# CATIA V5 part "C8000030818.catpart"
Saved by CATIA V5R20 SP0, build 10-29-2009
Part number: C8000030818
Source: Unknown
Property "A": "30"
Property "ARTICLENO": "C8000030818"
Property "B": "13"
Property "BOMINFO": "C8000030818"
Property "C": "46"
Property "CA": "C8000030818"
Property "D1": "38"
Property "DES": "ROTATING EYEBOLT WITH RING Ton 0,3 M8x18"
Property "E": "50"
Property "H": "105"
Property "L": "18"
Property "LINA": "C8000030818"
Property "NB": "C8000030818"
Property "NBSYN": "$CODE."
Property "NN": "C800"
Property "NT": "Rotating eyebolt with ring"
Property "SIZE": "M8"
Property "SUPPLIER": "CF"
Property "SW": "30"
Property "WEIGHT": "480"
Property "WLL": "0.30"
Bounding box of the stored display mesh (mm): x -27.837 to 28, y -18 to 117.837, z -19 to 19
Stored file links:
  C:\Users\Utente\Desktop\3D files 800\C8000030818.catpart
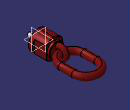
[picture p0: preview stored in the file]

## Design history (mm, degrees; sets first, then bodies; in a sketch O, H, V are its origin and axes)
Body1 "Geometry.1" (main body)
  Solid1 "C8000030818.catpart": solid without history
